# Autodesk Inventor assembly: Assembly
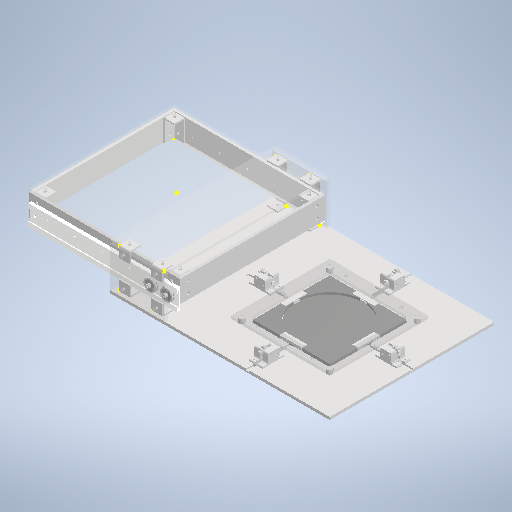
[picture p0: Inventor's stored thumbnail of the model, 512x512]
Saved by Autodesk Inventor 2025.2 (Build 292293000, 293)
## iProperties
Created: 2025-09
Part Number: Assembly
Document SubType Name: Assembly
Designer: tyler
Author: tyler
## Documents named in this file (21)
- C:\School Work\MIT ASP\6-9020 HTMAA\Final Project\Assembly.iam
- C:\School Work\MIT ASP\6-9020 HTMAA\Final Project\BasePlate.ipt
- C:\School Work\MIT ASP\6-9020 HTMAA\Final Project\Bearing.ipt
- C:\School Work\MIT ASP\6-9020 HTMAA\Final Project\Bracket.ipt
- C:\School Work\MIT ASP\6-9020 HTMAA\Final Project\Contact_6inPlate.ipt
- C:\School Work\MIT ASP\6-9020 HTMAA\Final Project\Frame_6inWafer.ipt
- C:\School Work\MIT ASP\6-9020 HTMAA\Final Project\GearSmall.ipt
- C:\School Work\MIT ASP\6-9020 HTMAA\Final Project\InnerBearing.ipt
- C:\School Work\MIT ASP\6-9020 HTMAA\Final Project\LinearSlide.ipt
- C:\School Work\MIT ASP\6-9020 HTMAA\Final Project\MaskFrame.ipt
- C:\School Work\MIT ASP\6-9020 HTMAA\Final Project\OuterBearing.ipt
- C:\School Work\MIT ASP\6-9020 HTMAA\Final Project\Rail.ipt
- C:\School Work\MIT ASP\6-9020 HTMAA\Final Project\Standoff.ipt
- C:\School Work\MIT ASP\6-9020 HTMAA\Final Project\Top.ipt
- C:\School Work\MIT ASP\6-9020 HTMAA\Final Project\Wall.ipt
- C:\School Work\MIT ASP\6-9020 HTMAA\Final Project\GearMount.ipt
- C:\School Work\MIT ASP\6-9020 HTMAA\Final Project\LightBoxRail.ipt
- C:\School Work\MIT ASP\6-9020 HTMAA\Final Project\LightBoxWall.ipt
- C:\School Work\MIT ASP\6-9020 HTMAA\Final Project\LightBoxTop.ipt
- C:\School Work\MIT ASP\6-9020 HTMAA\Final Project\TriBracket.ipt
- C:\School Work\MIT ASP\6-9020 HTMAA\Final Project\ContactStay_6inPlate.ipt
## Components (73 placed, 20 different names)
1. BasePlate:1
2. Bearing:1 — Mate:78, Mate:110, Flush:9, Flush:10
3. Bearing:2 — Mate:77, Flush:7, Flush:8, Mate:109
4. Bearing:5 — Mate:74, Flush:3, Flush:4, Mate:107
5. Bearing:6 — Mate:72, Flush:1, Flush:2, Mate:105
6. Bracket:1 — Mate:64, Mate:71, Mate:125
7. Bracket:2 — Mate:65, Mate:70, Mate:126
8. Bracket:3 — Mate:66, Mate:69, Mate:128
9. Bracket:4 — Mate:67, Mate:68, Mate:127
10. Bracket:5 — Mate:34, Mate:54, Mate:58
11. Bracket:6 — Mate:33, Mate:52, Mate:62
12. Bracket:7 — Mate:32, Mate:55, Mate:59
13. Bracket:8 — Mate:31, Mate:53, Mate:63
14. Contact_6inPlate:1 — Mate:137, Mate:138, Mate:139
15. Contact_6inPlate:2 — Mate:131, Mate:132, Mate:133
16. Contact_6inPlate:3 — Mate:43, Mate:129, Mate:130
17. Contact_6inPlate:4 — Mate:134, Mate:135, Mate:136
18. Frame_6inWafer:1 — Mate:43, Mate:44, Mate:45, Mate:46, Mate:129, Mate:130, Mate:131, Mate:132, Mate:133, Mate:134, Mate:135, Mate:136, Mate:138, Mate:139, Mate:193, Mate:194, Mate:195, Mate:196, Mate:197, Mate:198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
19. GearSmall:1 — Mate:51, Mate:180
20. GearSmall:2 — Mate:88, Mate:177
21. GearSmall:3 — Mate:93, Mate:181
22. GearSmall:4 — Mate:49, Mate:183
23. InnerBearing:1 — Mate:72, Mate:104, Flush:1, Mate:106
24. InnerBearing:4 — Mate:74, Flush:3, Mate:112, Mate:113
25. InnerBearing:5 — Mate:77, Flush:7, Mate:115
26. InnerBearing:6 — Mate:78, Flush:10, Mate:114
27. LinearSlide:1 — Mate:101, Mate:102
28. LinearSlide:2 — Mate:99, Mate:100
29. LinearSlide:3 — Mate:97, Mate:98
30. LinearSlide:4 — Mate:95, Mate:96
31. MaskFrame:1 — Mate:39, Mate:40, Mate:41, Mate:42
32. OuterBearing:1 — Flush:8, Mate:109, Tangent:4
33. OuterBearing:2 — Mate:110, Flush:9, Tangent:3, Mate:122
34. OuterBearing:3 — Flush:2, Mate:105, Tangent:1
35. OuterBearing:5 — Flush:4, Mate:107, Mate:121, Tangent:2
36. Rail:1 — Mate:121, Tangent:1, Tangent:2, Mate:172, Mate:173
37. Rail:2 — Tangent:3, Mate:122, Tangent:4, Mate:174, Mate:175
38. Standoff:1 — Mate:30, Mate:37, Mate:41
39. Standoff:2 — Mate:29, Mate:36, Mate:39, Mate:42
40. Standoff:3 — Mate:27, Mate:35
41. Standoff:4 — Mate:28, Mate:38, Mate:40
42. Top:1 — Mate:123, Mate:124, Mate:125, Mate:126, Mate:127, Mate:128
43. Wall:1 — Mate:56, Mate:57, Mate:58, Mate:59, Mate:66, Mate:67, Mate:68, Mate:69, Mate:104, Mate:106, Mate:112, Mate:113
44. Wall:2 — Mate:60, Mate:61, Mate:62, Mate:63, Mate:64, Mate:65, Mate:70, Mate:71, Mate:114, Mate:115, Mate:123, Mate:124
45. GearMount:1 — Mate:1, Mate:10, Mate:11, Mate:49, Mate:183, Mate:191, Mate:192
46. GearMount:2 — Mate:7, Mate:8, Mate:9, Mate:93, Mate:181, Mate:187, Mate:188
47. GearMount:3 — Mate:12, Mate:13, Mate:14
48. GearMount:4 — Mate:4, Mate:5, Mate:6, Mate:180, Mate:185, Mate:186
49. GearMount:5 — Mate:21, Mate:22, Mate:23, Mate:88, Mate:177, Mate:189, Mate:190
50. GearMount:6 — Mate:24, Mate:25, Mate:26
51. GearMount:7 — Mate:18, Mate:19, Mate:20, Mate:51
52. GearMount:8 — Mate:15, Mate:16, Mate:17
53. LightBoxRail:1
54. LightBoxRail:2
55. LightBoxWall:1
56. LightBoxWall:2 — Mate:162, Mate:165, Mate:166, Mate:169, Mate:170, Mate:171
57. LightBoxTop:1 — Flush:14, Flush:15, Mate:176
58. Bracket:9 — Mate:140, Mate:142, Mate:148, Mate:150
59. Bracket:10 — Mate:141, Mate:143, Mate:170
60. Bracket:11 — Mate:152, Mate:155, Mate:156, Mate:157
61. Bracket:12 — Mate:160, Mate:162, Mate:168, Mate:169
62. TriBracket:1 — Mate:146, Mate:171, Flush:13
63. TriBracket:2 — Mate:153, Mate:154, Mate:158, Mate:159
64. TriBracket:3 — Mate:164, Mate:165, Mate:166, Mate:167
65. TriBracket:4 — Mate:144, Mate:145, Mate:149, Mate:151
66. GearSmall:5 — Mate:185, Mate:186
67. GearSmall:6 — Mate:187, Mate:188
68. GearSmall:7 — Mate:191, Mate:192
69. GearSmall:8 — Mate:189, Mate:190
70. ContactStay_6inPlate:1 — Mate:193, Mate:194
71. ContactStay_6inPlate:2 — Mate:195, Mate:196
72. ContactStay_6inPlate:3 — Mate:197, Mate:200
73. ContactStay_6inPlate:4 — Mate:198, Mate:199
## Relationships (178: Mate 163, Flush 11, Tangent 4)
- Mate:1: GearMount:1
- Mate:4: GearMount:4
- Mate:5: GearMount:4
- Mate:6: GearMount:4
- Mate:7: GearMount:2
- Mate:8: GearMount:2
- Mate:9: GearMount:2
- Mate:10: GearMount:1
- Mate:11: GearMount:1
- Mate:12: GearMount:3
- Mate:13: GearMount:3
- Mate:14: GearMount:3
- Mate:15: GearMount:8
- Mate:16: GearMount:8
- Mate:17: GearMount:8
- Mate:18: GearMount:7
- Mate:19: GearMount:7
- Mate:20: GearMount:7
- Mate:21: GearMount:5
- Mate:22: GearMount:5
- Mate:23: GearMount:5
- Mate:24: GearMount:6
- Mate:25: GearMount:6
- Mate:26: GearMount:6
- Mate:27: Standoff:3
- Mate:28: Standoff:4
- Mate:29: Standoff:2
- Mate:30: Standoff:1
- Mate:31: Bracket:8
- Mate:32: Bracket:7
- Mate:33: Bracket:6
- Mate:34: Bracket:5
- Mate:35: Standoff:3
- Mate:36: Standoff:2
- Mate:37: Standoff:1
- Mate:38: Standoff:4
- Mate:39: MaskFrame:1 ↔ Standoff:2
- Mate:40: MaskFrame:1 ↔ Standoff:4
- Mate:41: MaskFrame:1 ↔ Standoff:1
- Mate:42: MaskFrame:1 ↔ Standoff:2
- Mate:43: Contact_6inPlate:3 ↔ Frame_6inWafer:1
- Mate:44: Frame_6inWafer:1
- Mate:45: Frame_6inWafer:1
- Mate:46: Frame_6inWafer:1
- Mate:49: GearSmall:4 ↔ GearMount:1
- Mate:51: GearSmall:1 ↔ GearMount:7
- Mate:52: Bracket:6
- Mate:53: Bracket:8
- Mate:54: Bracket:5
- Mate:55: Bracket:7
- Mate:56: Wall:1
- Mate:57: Wall:1
- Mate:58: Bracket:5 ↔ Wall:1
- Mate:59: Bracket:7 ↔ Wall:1
- Mate:60: Wall:2
- Mate:61: Wall:2
- Mate:62: Bracket:6 ↔ Wall:2
- Mate:63: Bracket:8 ↔ Wall:2
- Mate:64: Bracket:1 ↔ Wall:2
- Mate:65: Bracket:2 ↔ Wall:2
- Mate:66: Bracket:3 ↔ Wall:1
- Mate:67: Bracket:4 ↔ Wall:1
- Mate:68: Bracket:4 ↔ Wall:1
- Mate:69: Bracket:3 ↔ Wall:1
- Mate:70: Bracket:2 ↔ Wall:2
- Mate:71: Bracket:1 ↔ Wall:2
- Mate:72: Bearing:6 ↔ InnerBearing:1
- Mate:74: Bearing:5 ↔ InnerBearing:4
- Mate:77: Bearing:2 ↔ InnerBearing:5
- Mate:78: Bearing:1 ↔ InnerBearing:6
- Mate:88: GearSmall:2 ↔ GearMount:5
- Mate:93: GearSmall:3 ↔ GearMount:2
- Mate:95: LinearSlide:4
- Mate:96: LinearSlide:4
- Mate:97: LinearSlide:3
- Mate:98: LinearSlide:3
- Mate:99: LinearSlide:2
- Mate:100: LinearSlide:2
- Mate:101: LinearSlide:1
- Mate:102: LinearSlide:1
- Mate:104: InnerBearing:1 ↔ Wall:1
- Flush:1: Bearing:6 ↔ InnerBearing:1
- Flush:2: Bearing:6 ↔ OuterBearing:3
- Mate:105: Bearing:6 ↔ OuterBearing:3
- Mate:106: InnerBearing:1 ↔ Wall:1
- Flush:3: Bearing:5 ↔ InnerBearing:4
- Flush:4: Bearing:5 ↔ OuterBearing:5
- Mate:107: Bearing:5 ↔ OuterBearing:5
- Flush:7: Bearing:2 ↔ InnerBearing:5
- Flush:8: Bearing:2 ↔ OuterBearing:1
- Mate:109: Bearing:2 ↔ OuterBearing:1
- Mate:110: Bearing:1 ↔ OuterBearing:2
- Flush:9: Bearing:1 ↔ OuterBearing:2
- Flush:10: Bearing:1 ↔ InnerBearing:6
- Mate:112: InnerBearing:4 ↔ Wall:1
- Mate:113: InnerBearing:4 ↔ Wall:1
- Mate:114: InnerBearing:6 ↔ Wall:2
- Mate:115: InnerBearing:5 ↔ Wall:2
- Mate:121: OuterBearing:5 ↔ Rail:1
- Tangent:1: OuterBearing:3 ↔ Rail:1
- Tangent:2: OuterBearing:5 ↔ Rail:1
- Tangent:3: OuterBearing:2 ↔ Rail:2
- Mate:122: OuterBearing:2 ↔ Rail:2
- Tangent:4: OuterBearing:1 ↔ Rail:2
- Mate:123: Top:1 ↔ Wall:2
- Mate:124: Top:1 ↔ Wall:2
- Mate:125: Bracket:1 ↔ Top:1
- Mate:126: Bracket:2 ↔ Top:1
- Mate:127: Bracket:4 ↔ Top:1
- Mate:128: Bracket:3 ↔ Top:1
- Mate:129: Contact_6inPlate:3 ↔ Frame_6inWafer:1
- Mate:130: Contact_6inPlate:3 ↔ Frame_6inWafer:1
- Mate:131: Contact_6inPlate:2 ↔ Frame_6inWafer:1
- Mate:132: Contact_6inPlate:2 ↔ Frame_6inWafer:1
- Mate:133: Contact_6inPlate:2 ↔ Frame_6inWafer:1
- Mate:134: Contact_6inPlate:4 ↔ Frame_6inWafer:1
- Mate:135: Contact_6inPlate:4 ↔ Frame_6inWafer:1
- Mate:136: Contact_6inPlate:4 ↔ Frame_6inWafer:1
- Mate:137: Contact_6inPlate:1
- Mate:138: Contact_6inPlate:1 ↔ Frame_6inWafer:1
- Mate:139: Contact_6inPlate:1 ↔ Frame_6inWafer:1
- Mate:140: Bracket:9
- Mate:141: Bracket:10
- Mate:142: Bracket:9
- Mate:143: Bracket:10
- Mate:144: TriBracket:4
- Mate:145: TriBracket:4
- Mate:146: TriBracket:1
- Mate:148: Bracket:9
- Mate:149: TriBracket:4
- Mate:150: Bracket:9
- Mate:151: TriBracket:4
- Mate:152: Bracket:11
- Mate:153: TriBracket:2
- Mate:154: TriBracket:2
- Mate:155: Bracket:11
- Mate:156: Bracket:11
- Mate:157: Bracket:11
- Mate:158: TriBracket:2
- Mate:159: TriBracket:2
- Mate:160: Bracket:12
- Mate:162: LightBoxWall:2 ↔ Bracket:12
- Mate:164: TriBracket:3
- Mate:165: LightBoxWall:2 ↔ TriBracket:3
- Mate:166: LightBoxWall:2 ↔ TriBracket:3
- Mate:167: TriBracket:3
- Mate:168: Bracket:12
- Mate:169: LightBoxWall:2 ↔ Bracket:12
- Mate:170: LightBoxWall:2 ↔ Bracket:10
- Mate:171: LightBoxWall:2 ↔ TriBracket:1
- Flush:13: TriBracket:1
- Mate:172: Rail:1
- Mate:173: Rail:1
- Mate:174: Rail:2
- Mate:175: Rail:2
- Flush:14: LightBoxTop:1
- Flush:15: LightBoxTop:1
- Mate:176: LightBoxTop:1
- Mate:177: GearSmall:2 ↔ GearMount:5
- Mate:180: GearSmall:1 ↔ GearMount:4
- Mate:181: GearSmall:3 ↔ GearMount:2
- Mate:183: GearSmall:4 ↔ GearMount:1
- Mate:185: GearMount:4 ↔ GearSmall:5
- Mate:186: GearMount:4 ↔ GearSmall:5
- Mate:187: GearMount:2 ↔ GearSmall:6
- Mate:188: GearMount:2 ↔ GearSmall:6
- Mate:189: GearMount:5 ↔ GearSmall:8
- Mate:190: GearMount:5 ↔ GearSmall:8
- Mate:191: GearMount:1 ↔ GearSmall:7
- Mate:192: GearMount:1 ↔ GearSmall:7
- Mate:193: Frame_6inWafer:1 ↔ ContactStay_6inPlate:1
- Mate:194: Frame_6inWafer:1 ↔ ContactStay_6inPlate:1
- Mate:195: Frame_6inWafer:1 ↔ ContactStay_6inPlate:2
- Mate:196: Frame_6inWafer:1 ↔ ContactStay_6inPlate:2
- Mate:197: Frame_6inWafer:1 ↔ ContactStay_6inPlate:3
- Mate:198: Frame_6inWafer:1 ↔ ContactStay_6inPlate:4
- Mate:199: Frame_6inWafer:1 ↔ ContactStay_6inPlate:4
- Mate:200: Frame_6inWafer:1 ↔ ContactStay_6inPlate:3
